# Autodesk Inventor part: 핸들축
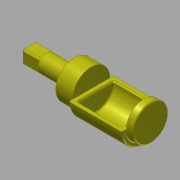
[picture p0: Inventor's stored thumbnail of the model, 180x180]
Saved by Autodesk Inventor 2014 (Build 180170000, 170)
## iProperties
Created: 2018-01
Part Number: 핸들축
Material: 강철, 연강
Document SubType Name: Modeling
Designer: mduedu
Density: 1 g/cm^3
Appearance: 노란색
Author: mduedu
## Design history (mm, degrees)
sketch "스케치1"
  geometry: L1 (0, 0)-(-38, 0); L2 (-38, 0)-(-38, -7.5); L3 (-38, -7.5)-(0, -7.5); L4 (0, -7.5)-(0, 0); L5 (-38, 0)-(-53, 0); L6 (-53, 0)-(-53, -16); L7 (-53, -16)-(-38, -16); L8 (-38, -16)-(-38, 0); L9 (-53, 0)-(-98, 0); L10 (-98, 0)-(-98, -19); L11 (-98, -19)-(-53, -19); L12 (-53, -19)-(-53, 0); L13 (-98, 0)-(-104, 0); L14 (-104, 0)-(-104, -15); L15 (-104, -15)-(-98, -15); L16 (-98, -15)-(-98, 0)
  constraints: 32 end point, 8 parallel, 4 horizontal, 4 perpendicular
  dimensions: "d0" = 6 distance of L14.end L15.end; "d2" = 30 diameter of L15 L13; "d3" = 32 diameter of L7 L5; "d4" = 15 distance of L6.end L7.end; "d5" = 45 distance of L10.end L11.end; "d6" = 38 diameter of L11 L9; "d7" = 38 distance of L2.end L3.end; "d8" = 15 diameter of L3 L1
revolve "회전1" sketch "스케치1" stored, may be unused: angle "d9" = 90 deg
sketch "스케치2"
  geometry: L1 (0, -7.5)-(0, 7.5) reference; L2 (0, 7.5)-(38, 7.5) reference; L3 (38, 7.5)-(38, 16) reference; L4 (38, 16)-(53, 16) reference; L5 (53, 16)-(53, 19) reference; L6 (53, 19)-(98, 19) reference; L7 (98, 19)-(98, 15) reference; L8 (98, 15)-(104, 15) reference; L9 (104, 15)-(104, -15) reference; L10 (104, -15)-(98, -15) reference; L11 (98, -15)-(98, -19) reference; L12 (98, -19)-(53, -19) reference; L13 (53, -19)-(53, -16) reference; L14 (53, -16)-(38, -16) reference; L15 (38, -16)-(38, -7.5) reference; L16 (38, -7.5)-(0, -7.5) reference; L17 (0, 0)-(104, 0); L18 (53, 19)-(53, 0); L19 (98, 19)-(98, 0); L20 (98, 0)-(53, 0); L21 (98, 19)-(53, 19)
  constraints: 10 end point, 3 perpendicular, 2 point on line, 1 midpoint, 1 parallel
extrude "돌출1" cut sketch "스케치2" stored distance "d10" = 10; taper "d11" = 0 deg
sketch "스케치3"
  geometry: L1 (45, 0)-(0, 0) reference; L2 (45, 4)-(45, 0) reference; L3 (45, 34)-(45, 4) reference; L4 (45, 38)-(45, 34) reference; L5 (0, 38)-(45, 38) reference; L6 (0, 35)-(0, 38) reference; L7 (0, 35)-(0, 3) reference; L8 (0, 0)-(0, 3) reference; L9 (0, 19)-(45, 19); L10 (4, 19)-(41, 19); L11 (41, 19)-(41, 34); L12 (41, 34)-(4, 34); L13 (4, 34)-(4, 19); 1 further point
  constraints: 10 end point, 2 midpoint, 2 parallel, 1 horizontal, 1 perpendicular, 1 point on line
  dimensions: "d12" = 4 distance between parallel lines of L3 L11; "d13" = 4 distance between parallel lines of L7 L13; "d14" = 4 distance between parallel lines of L12 L5
revolve "회전2" sketch "스케치3" stored, may be unused: angle "d15" = 90 deg
fillet "모깎기1" dims "d16" = 1
chamfer "모따기1" distance "d17" = 1; stored, may be unused: second distance "d18" = 2, angle "d19" = 45 deg
sketch "스케치4"
  geometry: L1 (-6, -6)-(-4.5, -6); L2 (6, -6)-(6, -4.5); L3 (6, 6)-(4.5, 6); L4 (-6, 6)-(-6, 4.5); L5 (-6, -6)-(6, 6); L6 (6, -6)-(-6, 6); L7 (-4.5, 6)-(-6, 6); L8 (-6, 4.5)-(-6, -4.5); L9 (-6, -4.5)-(-6, -6); L10 (-4.5, -6)-(4.5, -6); L11 (4.5, -6)-(6, -6); L12 (6, -4.5)-(6, 4.5); L13 (6, 4.5)-(6, 6); L14 (4.5, 6)-(-4.5, 6); C1 r 7.5 at (0, 0) reference; 2 further points
  constraints: 28 end point, 18 parallel, 9 perpendicular, 3 horizontal, 2 midpoint, 1 coincident, 11 other
  dimensions: "d20" = 12 distance of L4.start L3.start; "d21" = 12 distance of L3.start L2.start (= d20)
extrude "돌출2" cut sketch "스케치4" distance "d22" = 15; taper "d23" = 0 deg
chamfer "모따기2" distance "d24" = 1; stored, may be unused: second distance "d25" = 2, angle "d26" = 45 deg
sketch "스케치5"
  geometry: 2 further points
  constraints: 1 coincident
hole "구멍1" sketch "스케치5" at (5, 4.153) diameter "d27" = 2.459; stored, may be unused: countersink angle "d31" = 90 deg, drill point angle "d33" = 120 deg; dims "d28" = 6.9, "d29" = 4, "d30" = 2, "d32" = 8.4
node "솔리드1"
node "투영된 루프1"
node "절단 모서리 투영1"
